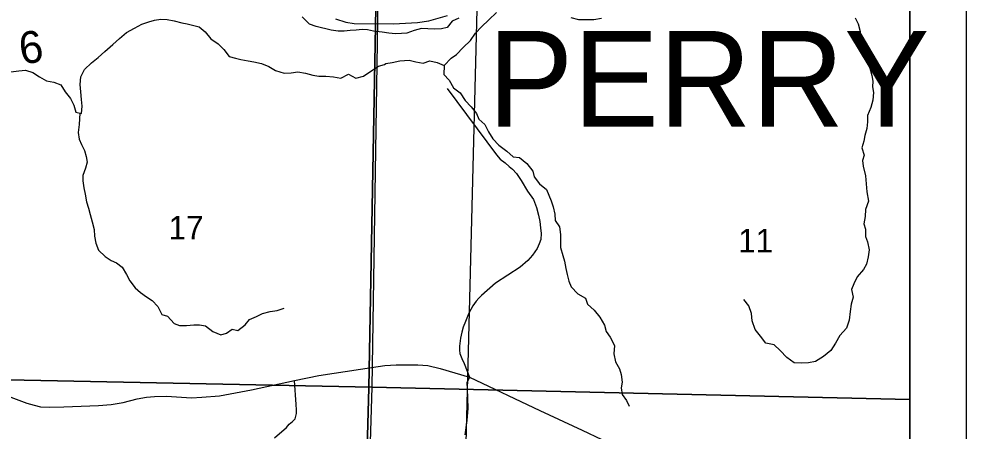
# Model space of a CAD drawing. Extents: x -19.9 to 41.9, y 0 to 32.3.
# Drawn here: x 7.317 to 9, y 18.865 to 19.598 of the extents above; entities that cross this region are included whole.
import ezdxf

# ---------------------------------------------------------------- set-up
doc = ezdxf.new("R2010")
doc.units = 0
for name, color, linetype in [('GM_X_Corporation', 7, 'Continuous'), ('GM_X_County_Road', 7, 'Continuous'), ('GM_X_Major_Lake', 7, 'Continuous'), ('GM_X_Minor_River', 7, 'Continuous'), ('GM_X_Section', 7, 'Continuous'), ('GM_X_Section_Text', 7, 'Continuous'), ('GM_X_State_Route', 7, 'Continuous'), ('GM_X_Township_Road', 7, 'Continuous'), ('GM_X_Township_Road_Text', 7, 'Continuous'), ('GM_X_Township_Text', 7, 'Continuous'), ('SH_Data', 7, 'Continuous')]:
    doc.layers.add(name, color=color, linetype=linetype)

msp = doc.modelspace()

# ---------------------------------------------------------------- linework, layer by layer
at = {"layer": 'GM_X_Corporation'}
for points in [[(8.9, 17.8974), (8.9, 20.9), (2.1, 20.9), (2.1, 17.918), (2.4715, 17.9106), (2.973, 17.9007), (3.7505, 17.884), (3.984, 17.879), (4.2613, 17.8672), (4.9169, 17.8392), (5.0192, 17.8403), (5.0257, 17.9637), (5.4954, 17.9559), (5.761, 17.9543), (5.9048, 17.9534), (6.2397, 17.9517), (6.2497, 17.9517), (6.3069, 17.9505), (6.7, 17.9422), (6.9468, 17.937), (7.3858, 17.9277), (7.5529, 17.9242), (7.9072, 17.9171)], [(8.9, 17.8974), (8.9, 20.9), (7.9833, 20.9), (7.9567, 19.9408), (7.9433, 19.1981), (7.9387, 18.9418), (7.9208, 18.3004), (7.9072, 17.9171)], [(7.9591, 19.9393), (7.944, 18.9426), (6.9135, 18.9637), (6.9305, 19.9596)], [(8.9, 18.9209), (8.9, 19.9267), (7.9591, 19.9393), (7.944, 18.9426)], [(6.9135, 18.9637), (7.944, 18.9426), (7.9129, 17.9261), (6.8905, 17.9411)], [(8.9, 17.9044), (8.9, 18.9209), (7.944, 18.9426), (7.9129, 17.9261)]]:
    msp.add_lwpolyline(points, close=True, dxfattribs=at)
msp.add_lwpolyline([(2.973, 17.9007), (3.7505, 17.884), (3.984, 17.879), (4.2613, 17.8672), (4.9169, 17.8392), (5.0192, 17.8403), (5.0257, 17.9637), (5.4954, 17.9559), (5.761, 17.9543), (5.9048, 17.9534), (6.2397, 17.9517), (6.2497, 17.9517), (6.3069, 17.9505), (6.7, 17.9422), (6.9468, 17.937), (7.3858, 17.9277), (7.5529, 17.9242), (7.9072, 17.9171), (7.9208, 18.3004), (7.9387, 18.9418), (7.9433, 19.1981), (7.9567, 19.9408), (7.9833, 20.9), (2.1, 20.9)], dxfattribs=at)
at = {"layer": 'GM_X_County_Road'}
msp.add_lwpolyline([(7.8792, 19.5982), (7.8977, 19.5919), (7.9126, 19.5897), (7.9823, 19.5894), (8.025, 19.5917), (8.0453, 19.5943), (8.0783, 19.604)], dxfattribs=at)
at = {"layer": 'GM_X_Major_Lake'}
for points in [[(7.4268, 19.4947), (7.433, 19.5077), (7.4457, 19.5196), (7.4573, 19.5293), (7.4693, 19.5402), (7.4836, 19.5525), (7.4952, 19.563), (7.5079, 19.5738), (7.5219, 19.5812), (7.535, 19.5887), (7.5475, 19.5927), (7.5574, 19.5959), (7.5691, 19.5972), (7.5801, 19.597), (7.5924, 19.5946), (7.6061, 19.591), (7.6156, 19.5889), (7.6275, 19.5864), (7.637, 19.5839), (7.6478, 19.575), (7.6579, 19.5623), (7.671, 19.5538), (7.6806, 19.5433), (7.6903, 19.5313), (7.7018, 19.5281), (7.7113, 19.5256), (7.7243, 19.5232), (7.7342, 19.5214), (7.7476, 19.5186), (7.761, 19.5135), (7.7729, 19.5062), (7.7878, 19.5011), (7.8007, 19.5021), (7.8124, 19.5038), (7.8262, 19.5014), (7.8392, 19.4978), (7.8498, 19.4961), (7.862, 19.4963), (7.8757, 19.4946), (7.8887, 19.4925), (7.9022, 19.4996), (7.9153, 19.4926), (7.9289, 19.4959), (7.942, 19.5052), (7.9556, 19.5138), (7.9666, 19.517)], [(8.0982, 19.5992), (8.0869, 19.5937), (8.0776, 19.5826), (8.0674, 19.5805), (8.0552, 19.5799), (8.0434, 19.5801), (8.0324, 19.5811), (8.0188, 19.5774), (8.0059, 19.5723), (7.9964, 19.5721), (7.9858, 19.5716), (7.974, 19.5725), (7.9622, 19.5742), (7.9469, 19.5762), (7.9363, 19.5783), (7.9268, 19.5789), (7.9161, 19.578), (7.9051, 19.5774), (7.8945, 19.5761), (7.8838, 19.5759), (7.8716, 19.578), (7.8449, 19.5844), (7.8331, 19.5887), (7.8199, 19.6018)], [(7.9666, 19.517), (7.9688, 19.5188), (7.9798, 19.5206), (7.9938, 19.5231), (8.0101, 19.5245), (8.022, 19.5213), (8.0349, 19.5193), (8.0467, 19.5233), (8.06, 19.5204), (8.0726, 19.5153), (8.0846, 19.5281), (8.0944, 19.5347), (8.1063, 19.547), (8.119, 19.5594), (8.128, 19.5724), (8.1388, 19.5836), (8.1519, 19.5963), (8.1657, 19.6095)], [(8.2974, 19.6007), (8.3111, 19.5971), (8.3248, 19.597), (8.3385, 19.5968), (8.3522, 19.5993)], [(7.3023, 19.5036), (7.3167, 19.5057), (7.3281, 19.5067), (7.3415, 19.5027), (7.3534, 19.495), (7.3657, 19.4876), (7.3786, 19.4851), (7.3909, 19.4808), (7.3987, 19.4684), (7.4084, 19.4564), (7.4143, 19.4444), (7.4179, 19.4319), (7.4278, 19.4294), (7.4291, 19.4424), (7.4278, 19.4545), (7.4264, 19.4681), (7.4255, 19.481), (7.4268, 19.4947)]]:
    msp.add_lwpolyline(points, dxfattribs=at)
at = {"layer": 'GM_X_Minor_River'}
for points in [[(8.8031, 19.5999), (8.8082, 19.5893), (8.8119, 19.5754), (8.8125, 19.5625), (8.8161, 19.5493), (8.8205, 19.5357), (8.8245, 19.5233), (8.8285, 19.5124), (8.8325, 19.4973), (8.8342, 19.487), (8.8336, 19.4768), (8.8357, 19.467), (8.8344, 19.4533), (8.8308, 19.4404), (8.825, 19.4259), (8.8248, 19.4149), (8.8235, 19.4031), (8.82, 19.3905), (8.8186, 19.3806), (8.815, 19.3684), (8.8187, 19.3556), (8.8158, 19.3461), (8.8171, 19.3362), (8.8212, 19.3189), (8.8222, 19.3045), (8.8236, 19.2905), (8.8265, 19.2735), (8.8215, 19.2586), (8.8209, 19.2461), (8.8181, 19.2335), (8.8213, 19.2237), (8.8211, 19.2108), (8.8251, 19.201), (8.8276, 19.187), (8.8263, 19.1745), (8.8231, 19.1615), (8.818, 19.152), (8.8065, 19.1389), (8.8006, 19.1263), (8.7966, 19.1163), (8.7991, 19.1027), (8.7956, 19.0902), (8.7939, 19.0772), (8.7925, 19.0617), (8.7874, 19.0479)], [(8.0726, 19.5153), (8.0719, 19.4993), (8.0815, 19.4888), (8.0888, 19.4752), (8.1007, 19.4662), (8.1099, 19.453), (8.1203, 19.4413), (8.1299, 19.4296), (8.1341, 19.4194), (8.1445, 19.41), (8.1514, 19.3968), (8.1587, 19.3843), (8.1698, 19.3734), (8.1836, 19.3629), (8.1951, 19.3528), (8.2065, 19.3513), (8.2195, 19.3405), (8.2299, 19.3269), (8.2326, 19.3167), (8.2419, 19.3042), (8.2545, 19.2945), (8.2584, 19.2843), (8.2626, 19.2741), (8.2661, 19.2635), (8.2689, 19.2506), (8.2698, 19.2392), (8.2771, 19.2279), (8.2791, 19.2146), (8.2792, 19.2036), (8.2789, 19.1915), (8.2832, 19.1771), (8.2863, 19.1669), (8.2884, 19.154), (8.2911, 19.1434), (8.2939, 19.1316), (8.2981, 19.1214), (8.31, 19.109), (8.3234, 19.1008), (8.3273, 19.0902), (8.3388, 19.08), (8.3491, 19.0672), (8.3576, 19.0533), (8.3604, 19.0415), (8.3673, 19.0317), (8.375, 19.0166), (8.374, 19.0022), (8.3768, 18.9878), (8.3841, 18.9753), (8.3872, 18.9655), (8.3888, 18.9518), (8.387, 18.9416), (8.389, 18.9294), (8.3963, 18.9189), (8.401, 18.909)], [(7.4248, 19.4302), (7.4239, 19.4098), (7.4217, 19.3958), (7.4234, 19.384), (7.428, 19.3742), (7.433, 19.3636), (7.4362, 19.3534), (7.4378, 19.3428), (7.4352, 19.3321), (7.43, 19.3192), (7.4301, 19.3097), (7.4317, 19.2972), (7.4341, 19.2862), (7.4369, 19.2726), (7.44, 19.2612), (7.4435, 19.2502), (7.4467, 19.2366), (7.4502, 19.2234), (7.4511, 19.2112), (7.4531, 19.1991), (7.4581, 19.1862), (7.47, 19.1753), (7.4803, 19.1682), (7.4898, 19.1641), (7.4998, 19.1562), (7.5075, 19.143), (7.5137, 19.1321), (7.5233, 19.1193), (7.5328, 19.111), (7.5432, 19.1035), (7.5535, 19.0967), (7.5634, 19.0862), (7.5708, 19.0719), (7.5807, 19.0689), (7.5926, 19.0561), (7.6021, 19.0524), (7.6146, 19.0525), (7.6275, 19.0538), (7.6374, 19.0538), (7.6484, 19.052), (7.6611, 19.0419), (7.6755, 19.0356), (7.6854, 19.0387), (7.6956, 19.046), (7.7059, 19.0438), (7.7187, 19.0534), (7.7266, 19.0633), (7.7391, 19.0684), (7.7497, 19.0738), (7.7629, 19.0773), (7.7758, 19.0793), (7.788, 19.0832)], [(8.7874, 19.0479), (8.7756, 19.0349), (8.7677, 19.0211), (8.7598, 19.0078), (8.7466, 18.9974), (8.7323, 18.9882), (8.7201, 18.9862), (8.7076, 18.9857), (8.6943, 18.9863), (8.6813, 18.9957), (8.6698, 19.0081), (8.6587, 19.0179), (8.6443, 19.0212), (8.6347, 19.0333), (8.6254, 19.0453), (8.6196, 19.0605), (8.6184, 19.0737), (8.6141, 19.0874), (8.6049, 19.0987)]]:
    msp.add_lwpolyline(points, dxfattribs=at)
at = {"layer": 'GM_X_Section'}
msp.add_lwpolyline([(7.1171, 19.7458), (8.1335, 19.7322), (8.1079, 18.7263), (7.1021, 18.7492)], close=True, dxfattribs=at)
at = {"layer": 'GM_X_State_Route'}
msp.add_lwpolyline([(7.288, 18.93), (7.3309, 18.9144), (7.3436, 18.9105), (7.3551, 18.9076), (7.371, 18.9071), (7.3962, 18.9079), (7.4579, 18.9103), (7.4806, 18.9118), (7.502, 18.9155), (7.5267, 18.9221), (7.5433, 18.925), (7.5576, 18.9263), (7.5787, 18.9266), (7.6231, 18.924), (7.6414, 18.9252), (7.673, 18.9274), (7.7299, 18.9377), (7.8063, 18.9543), (7.8495, 18.9634), (7.9236, 18.975), (7.9668, 18.9812), (7.9868, 18.9825), (8.0255, 18.9827), (8.0434, 18.9812), (8.065, 18.9761), (8.1173, 18.9603), (8.2427, 18.9011), (8.3176, 18.8663), (8.3524, 18.8495)], dxfattribs=at)
at = {"layer": 'GM_X_Township_Road'}
for points in [[(8.0775, 19.474), (8.1654, 19.356), (8.1718, 19.3483), (8.1809, 19.3419), (8.1879, 19.3355), (8.1941, 19.3304), (8.2008, 19.3231), (8.209, 19.3105), (8.2204, 19.2913), (8.2313, 19.2767), (8.2367, 19.2626), (8.2402, 19.2488), (8.2425, 19.2372), (8.2437, 19.2265), (8.2451, 19.2162), (8.2441, 19.2056), (8.241, 19.198), (8.2379, 19.1893), (8.2294, 19.1775), (8.2211, 19.1681), (8.2075, 19.1561), (8.1638, 19.1276), (8.1386, 19.1059), (8.134, 19.1013), (8.1291, 19.096), (8.1233, 19.0873), (8.1165, 19.0741), (8.1101, 19.0596), (8.1062, 19.0495), (8.1039, 19.0408), (8.1016, 19.0299), (8.0996, 19.0156), (8.0996, 19.0084), (8.1002, 19.0028), (8.1039, 18.9935), (8.1077, 18.9851), (8.1173, 18.9603)], [(8.1173, 18.9603), (8.1127, 18.9503), (8.1131, 18.94), (8.1142, 18.9053), (8.1128, 18.8832), (8.1091, 18.858)], [(7.7709, 18.8526), (7.7923, 18.8711), (7.7967, 18.8771), (7.8026, 18.8816), (7.8074, 18.8865), (7.8097, 18.8957), (7.8102, 18.9024), (7.8092, 18.9118), (7.8063, 18.9543)]]:
    msp.add_lwpolyline(points, dxfattribs=at)
at = {"layer": 'SH_Data'}
for p, q in [((9, 21), (9, 14)), ((8.9, 20.9), (8.9, 14.1))]:
    msp.add_line(p, q, dxfattribs=at)

# ---------------------------------------------------------------- texts
at = {"layer": 'GM_X_Section_Text'}
for s, p in [('17', (7.5824, 19.2055)), ('11', (8.5949, 19.1825))]:
    msp.add_text(s, height=0.04186, rotation=0, dxfattribs=at).set_placement(p)
at = {"layer": 'GM_X_Township_Road_Text'}
msp.add_text('6', height=0.0568, rotation=8.2743, dxfattribs=at).set_placement((7.321, 19.5166))
at = {"layer": 'GM_X_Township_Text'}
msp.add_text('PERRY', height=0.17045, rotation=0, dxfattribs=at).set_placement((8.1498, 19.4061))

doc.saveas('drawing.dxf')
